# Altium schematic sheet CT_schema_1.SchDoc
size 522 x 473 mm
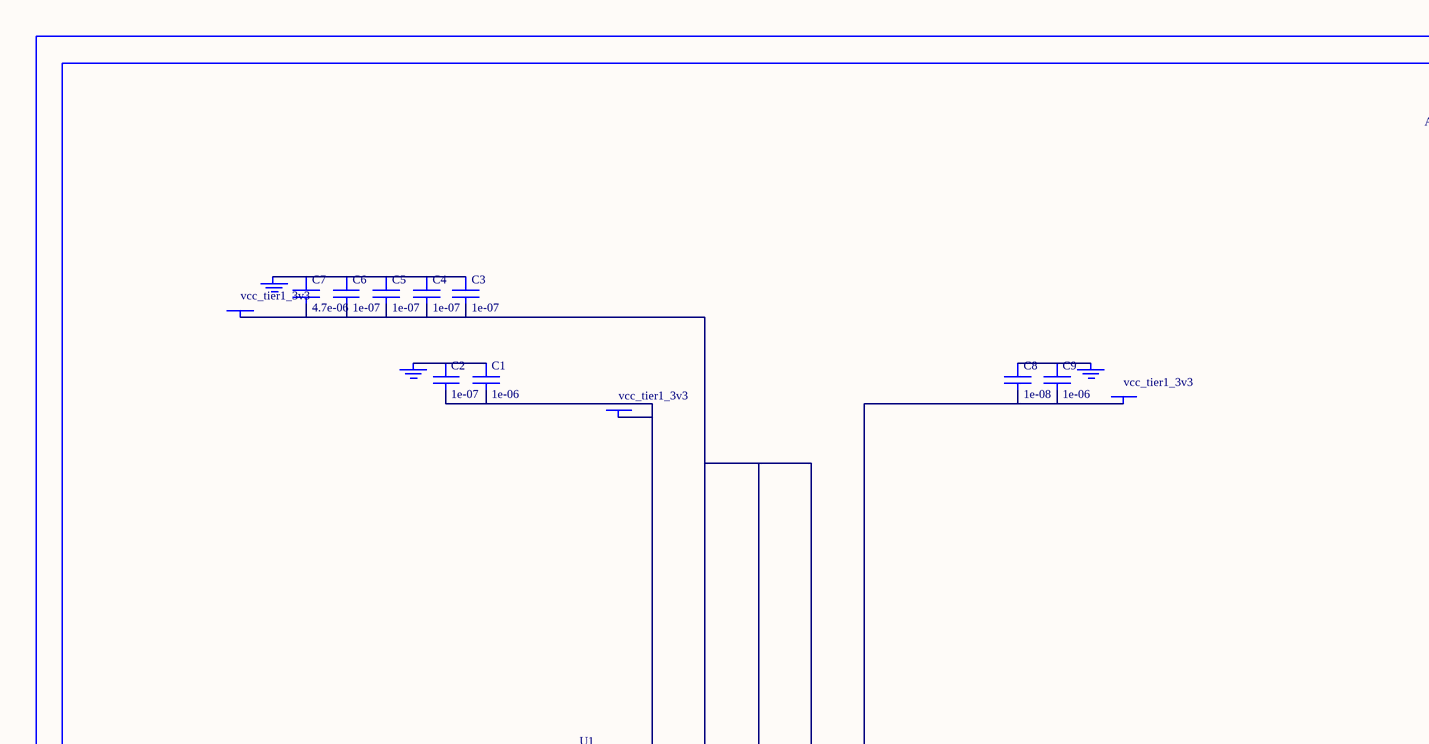
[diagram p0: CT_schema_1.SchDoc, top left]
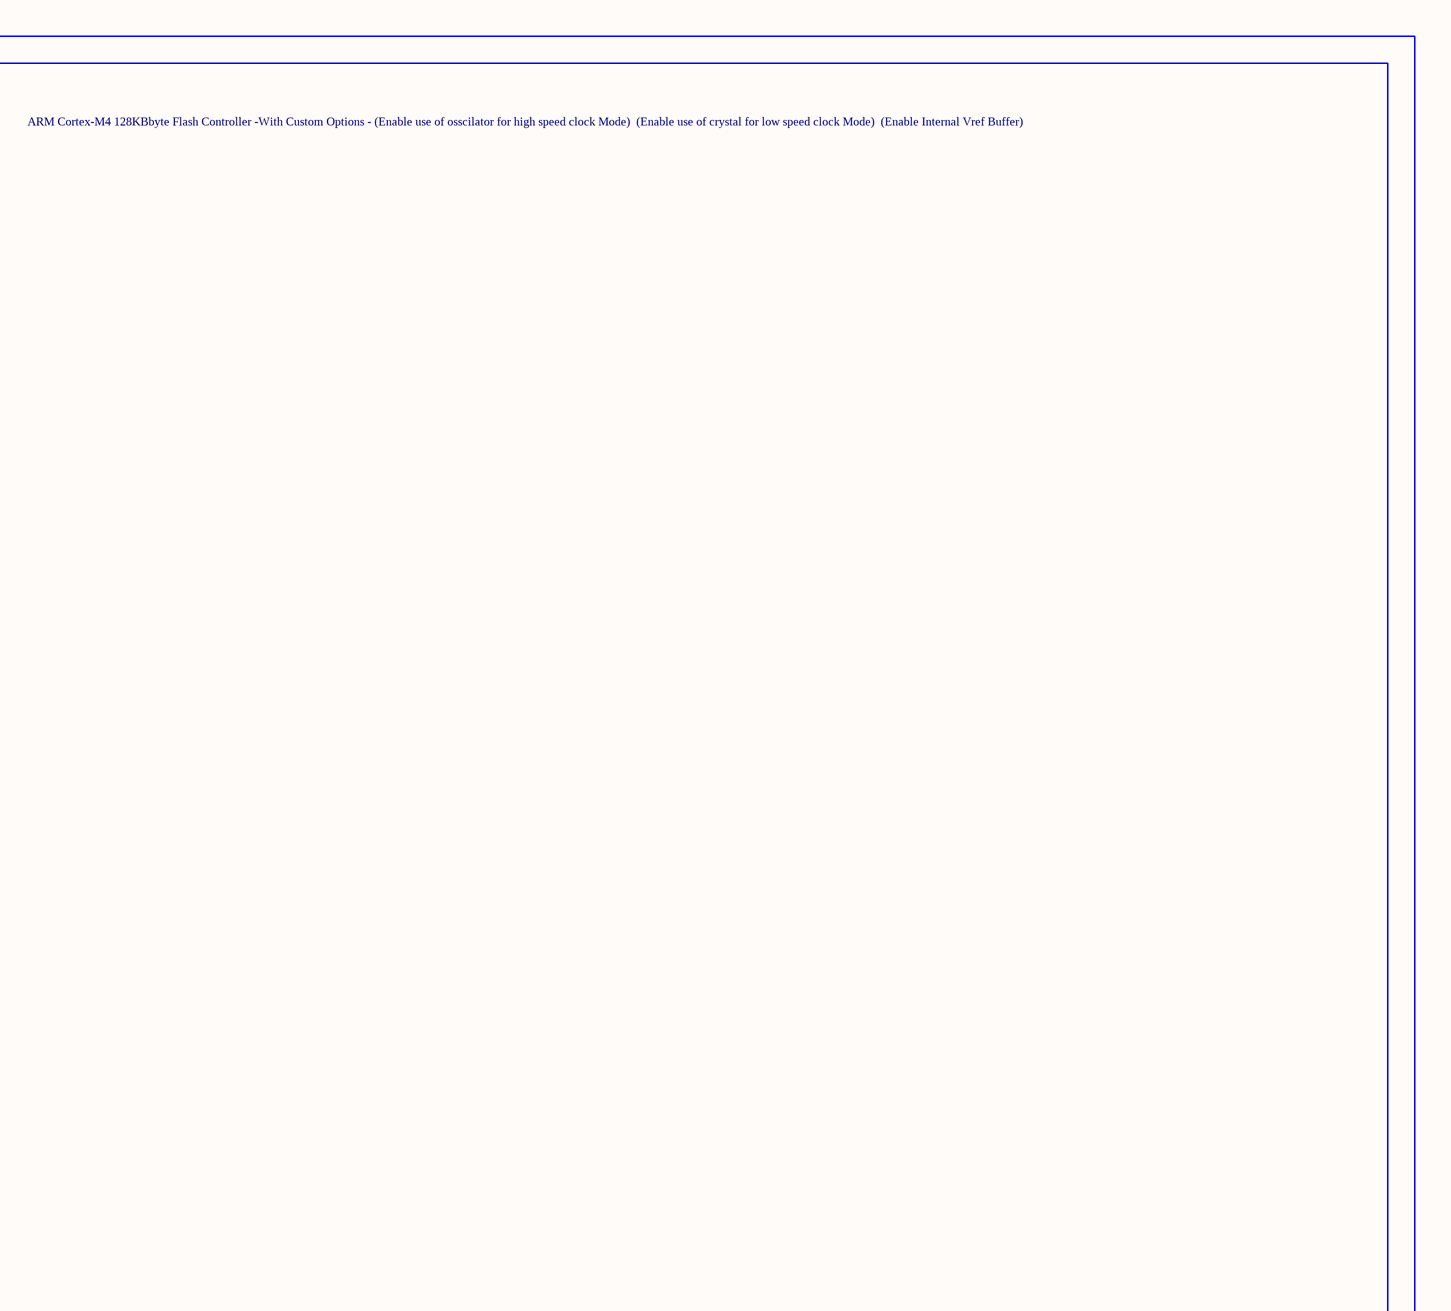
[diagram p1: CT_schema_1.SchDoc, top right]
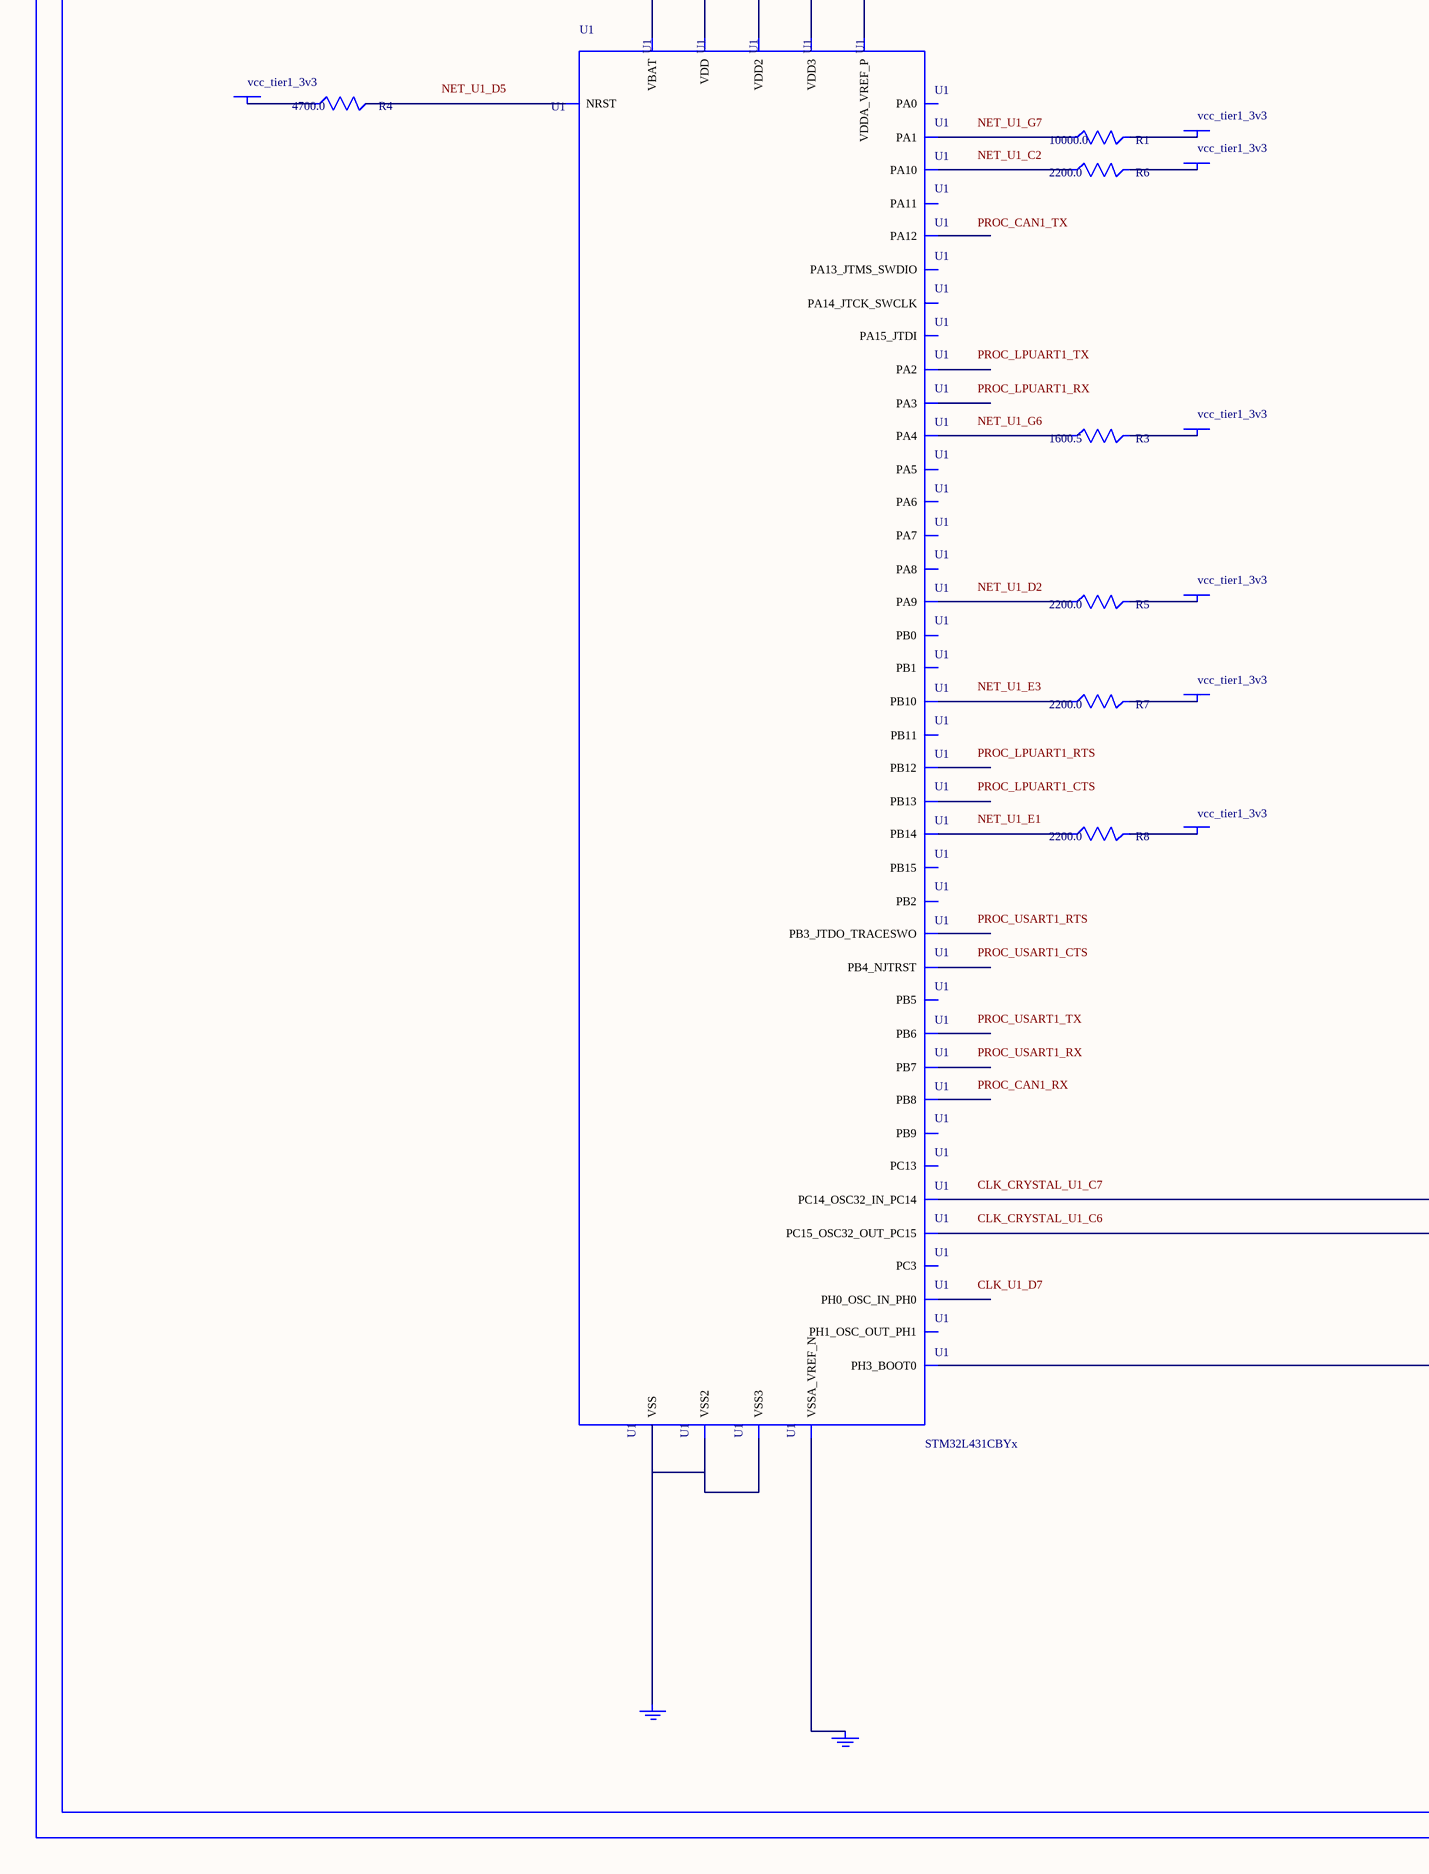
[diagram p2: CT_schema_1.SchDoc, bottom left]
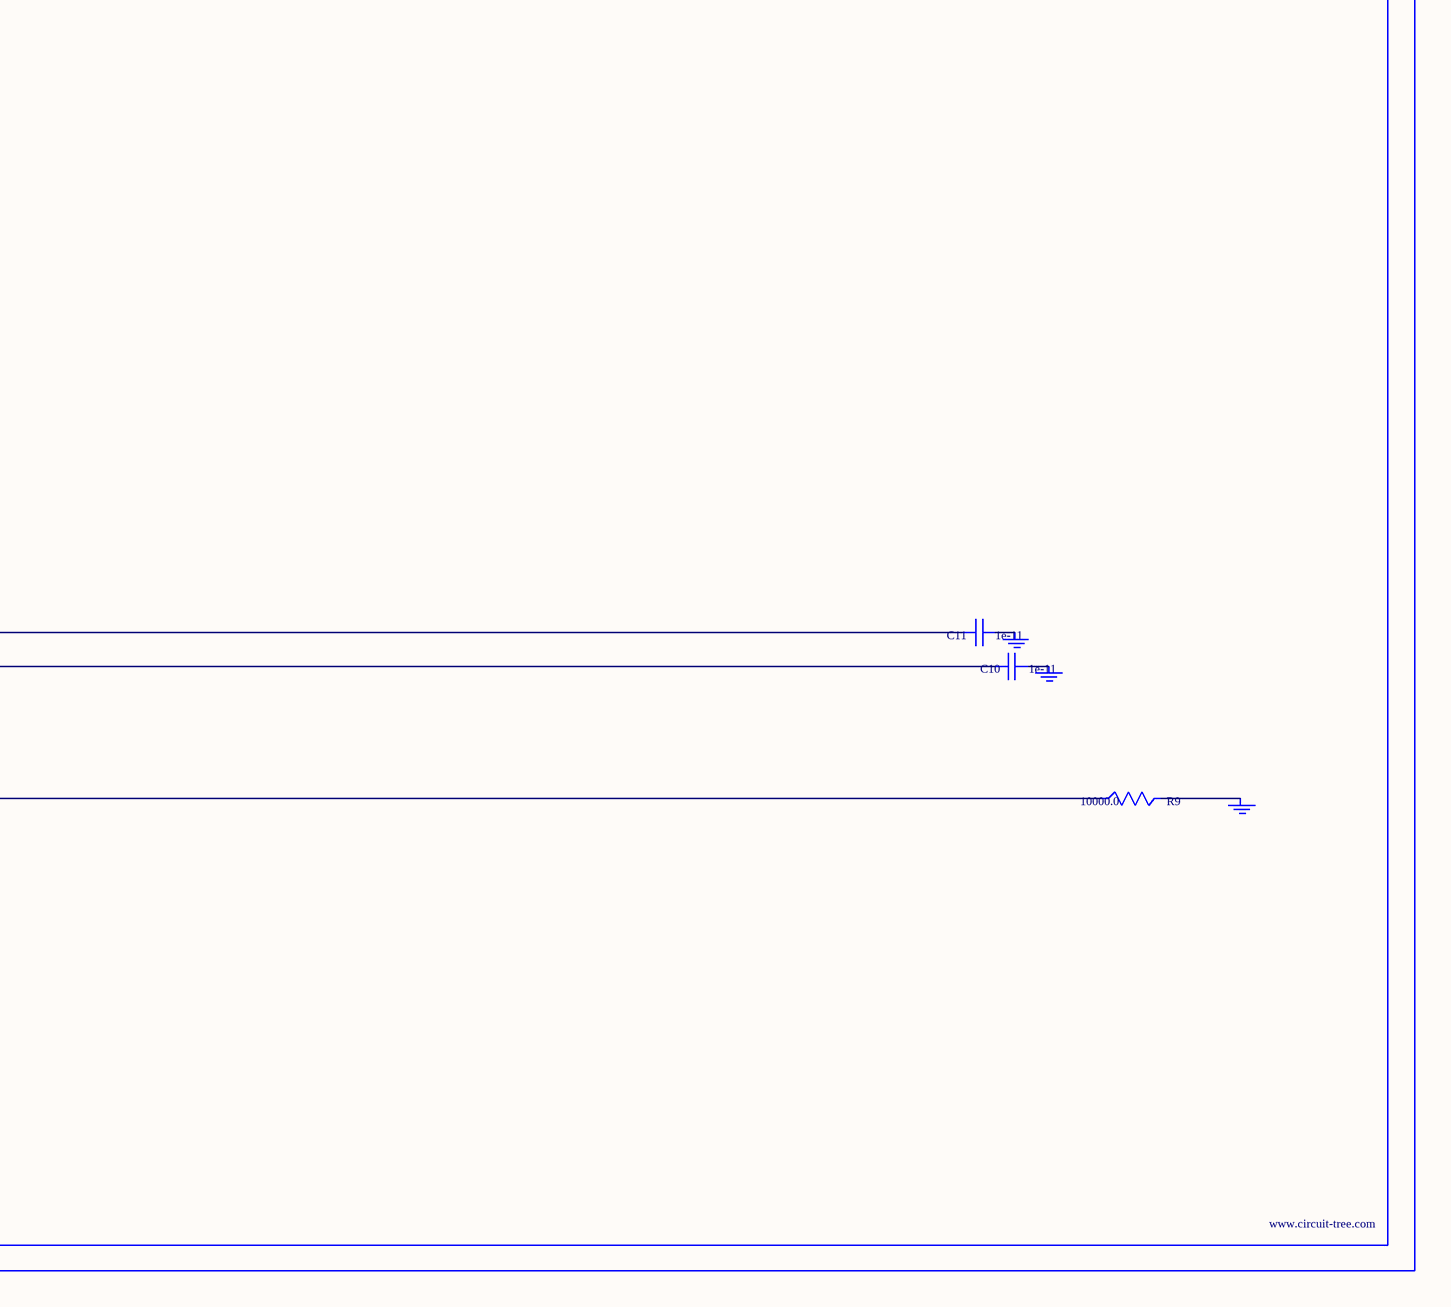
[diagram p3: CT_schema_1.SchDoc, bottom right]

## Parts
BORDER0  (no value)
C1  1e-06  [C0603]
C2  1e-07  [C0603]
C3  1e-07  [C0603]
C4  1e-07  [C0603]
C5  1e-07  [C0603]
C6  1e-07  [C0603]
C7  4.7e-06  [C0603]
C8  1e-08  [C0603]
C9  1e-06  [C0603]
C10  1e-11  [C0402]
C11  1e-11  [C0402]
GND_INSTANCE_0_0  (no value)
GND_INSTANCE_0_1  (no value)
GND_INSTANCE_0_2  (no value)
GND_INSTANCE_0_3  (no value)
GND_INSTANCE_0_4  (no value)
GND_INSTANCE_0_5  (no value)
GND_INSTANCE_0_6  (no value)
GND_INSTANCE_0_7  (no value)
POWER_INSTANCE_0_0  vcc_tier1_3v3
POWER_INSTANCE_0_1  vcc_tier1_3v3
POWER_INSTANCE_0_2  vcc_tier1_3v3
POWER_INSTANCE_0_3  vcc_tier1_3v3
POWER_INSTANCE_0_4  vcc_tier1_3v3
POWER_INSTANCE_0_5  vcc_tier1_3v3
POWER_INSTANCE_0_6  vcc_tier1_3v3
POWER_INSTANCE_0_7  vcc_tier1_3v3
POWER_INSTANCE_0_8  vcc_tier1_3v3
POWER_INSTANCE_0_9  vcc_tier1_3v3
R1  10000.0  [R0603]
R3  1600.5  [R0603]
R4  4700.0  [R0603]
R5  2200.0  [R0603]
R6  2200.0  [R0603]
R7  2200.0  [R0603]
R8  2200.0  [R0603]
R9  10000.0  [R0603]
U1  STM32L431CBYx  [WLCSP48]

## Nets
NetC1_1: C1.1 C2.1 GND_INSTANCE_0_0.0(GND)
NetC1_2: C1.2 C2.2 POWER_INSTANCE_0_0.0(PWR) U1.B6(VBAT)
NetC3_1: C3.1 C4.1 C5.1 C6.1 C7.1 GND_INSTANCE_0_1.0(GND)
NetC3_2: C3.2 C4.2 C5.2 C6.2 C7.2 POWER_INSTANCE_0_1.0(PWR) U1.A1(VDD) U1.A7(VDD2) U1.G1(VDD3)
NetC8_1: C8.1 C9.1 GND_INSTANCE_0_3.0(GND)
NetC8_2: C8.2 C9.2 POWER_INSTANCE_0_2.0(PWR) U1.F7(VDDA_VREF_P)
NetC10_1: C10.1 GND_INSTANCE_0_4.0(GND)
NetC10_2: C10.2 U1.C6(PC15_OSC32_OUT_PC15)
NetC11_1: C11.1 GND_INSTANCE_0_5.0(GND)
NetC11_2: C11.2 U1.C7(PC14_OSC32_IN_PC14)
NetGND_INSTANCE_0_2_0: GND_INSTANCE_0_2.0(GND) R9.2
NetGND_INSTANCE_0_6_0: GND_INSTANCE_0_6.0(GND) U1.E7(VSSA_VREF_N)
NetGND_INSTANCE_0_7_0: GND_INSTANCE_0_7.0(GND) U1.A6(VSS) U1.B1(VSS2) U1.G2(VSS3)
NetPOWER_INSTANCE_0_3_0: POWER_INSTANCE_0_3.0(PWR) R4.1
NetPOWER_INSTANCE_0_4_0: POWER_INSTANCE_0_4.0(PWR) R1.2
NetPOWER_INSTANCE_0_5_0: POWER_INSTANCE_0_5.0(PWR) R6.2
NetPOWER_INSTANCE_0_6_0: POWER_INSTANCE_0_6.0(PWR) R3.2
NetPOWER_INSTANCE_0_7_0: POWER_INSTANCE_0_7.0(PWR) R5.2
NetPOWER_INSTANCE_0_8_0: POWER_INSTANCE_0_8.0(PWR) R7.2
NetPOWER_INSTANCE_0_9_0: POWER_INSTANCE_0_9.0(PWR) R8.2
NetR1_1: R1.1 U1.G7(PA1)
NetR3_1: R3.1 U1.G6(PA4)
NetR4_2: R4.2 U1.D5(NRST)
NetR5_1: R5.1 U1.D2(PA9)
NetR6_1: R6.1 U1.C2(PA10)
NetR7_1: R7.1 U1.E3(PB10)
NetR8_1: R8.1 U1.E1(PB14)
NetR9_1: R9.1 U1.A5(PH3_BOOT0)

Not connected (* = marked no-connect by the designer): U1 A2(PA14_JTCK_SWCLK) A3(PB3_JTDO_TRACESWO) A4(PB4_NJTRST) B2(PA13_JTMS_SWDIO) B3(PA15_JTDI) B4(PB5) B5(PB8) B7(PC13) C1(PA11) C3(PA12) C4(PB6) C5(PB9) D1(PA8) D3(PB15) D4(PB7) D6(PH1_OSC_OUT_PH1) D7(PH0_OSC_IN_PH0) E2(PB13) E4(PA3) E5(PA2) E6(PC3) F1(PB12) F2(PB11) F3(PA7) F4(PA6) F5(PA5) F6(PA0) G3(PB2) G4(PB1) G5(PB0)

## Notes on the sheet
- Labels drawn without touching a wire or pin: CLK_CRYSTAL_U1_C6, CLK_CRYSTAL_U1_C7, CLK_U1_D7, NET_U1_C2, NET_U1_D2, NET_U1_D5, NET_U1_E1, NET_U1_E3, NET_U1_G6, NET_U1_G7, PROC_CAN1_RX, PROC_CAN1_TX, PROC_LPUART1_CTS, PROC_LPUART1_RTS, PROC_LPUART1_RX, PROC_LPUART1_TX, PROC_USART1_CTS, PROC_USART1_RTS, PROC_USART1_RX, PROC_USART1_TX

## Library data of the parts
BORDER0 = BORDER_PAGE0
C1 C9 = C0603C105K3RACTU
C2-C6 = 06035C104K4Z2A
C7 = GRM188R6YA475KE15D
C8 = 06035C103K4Z2A
C10 C11 = C0402C100K3GACTU
GND_INSTANCE_0_0-GND_INSTANCE_0_7 = GND
POWER_INSTANCE_0_0-POWER_INSTANCE_0_9 = PWR
R1 R9 = RC0603JR-0710KL
R3 = R3
R4 = RC0603JR-074K7L
R5-R8 = RC0603JR-072K2L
